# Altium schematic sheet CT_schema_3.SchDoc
size 313 x 185 mm
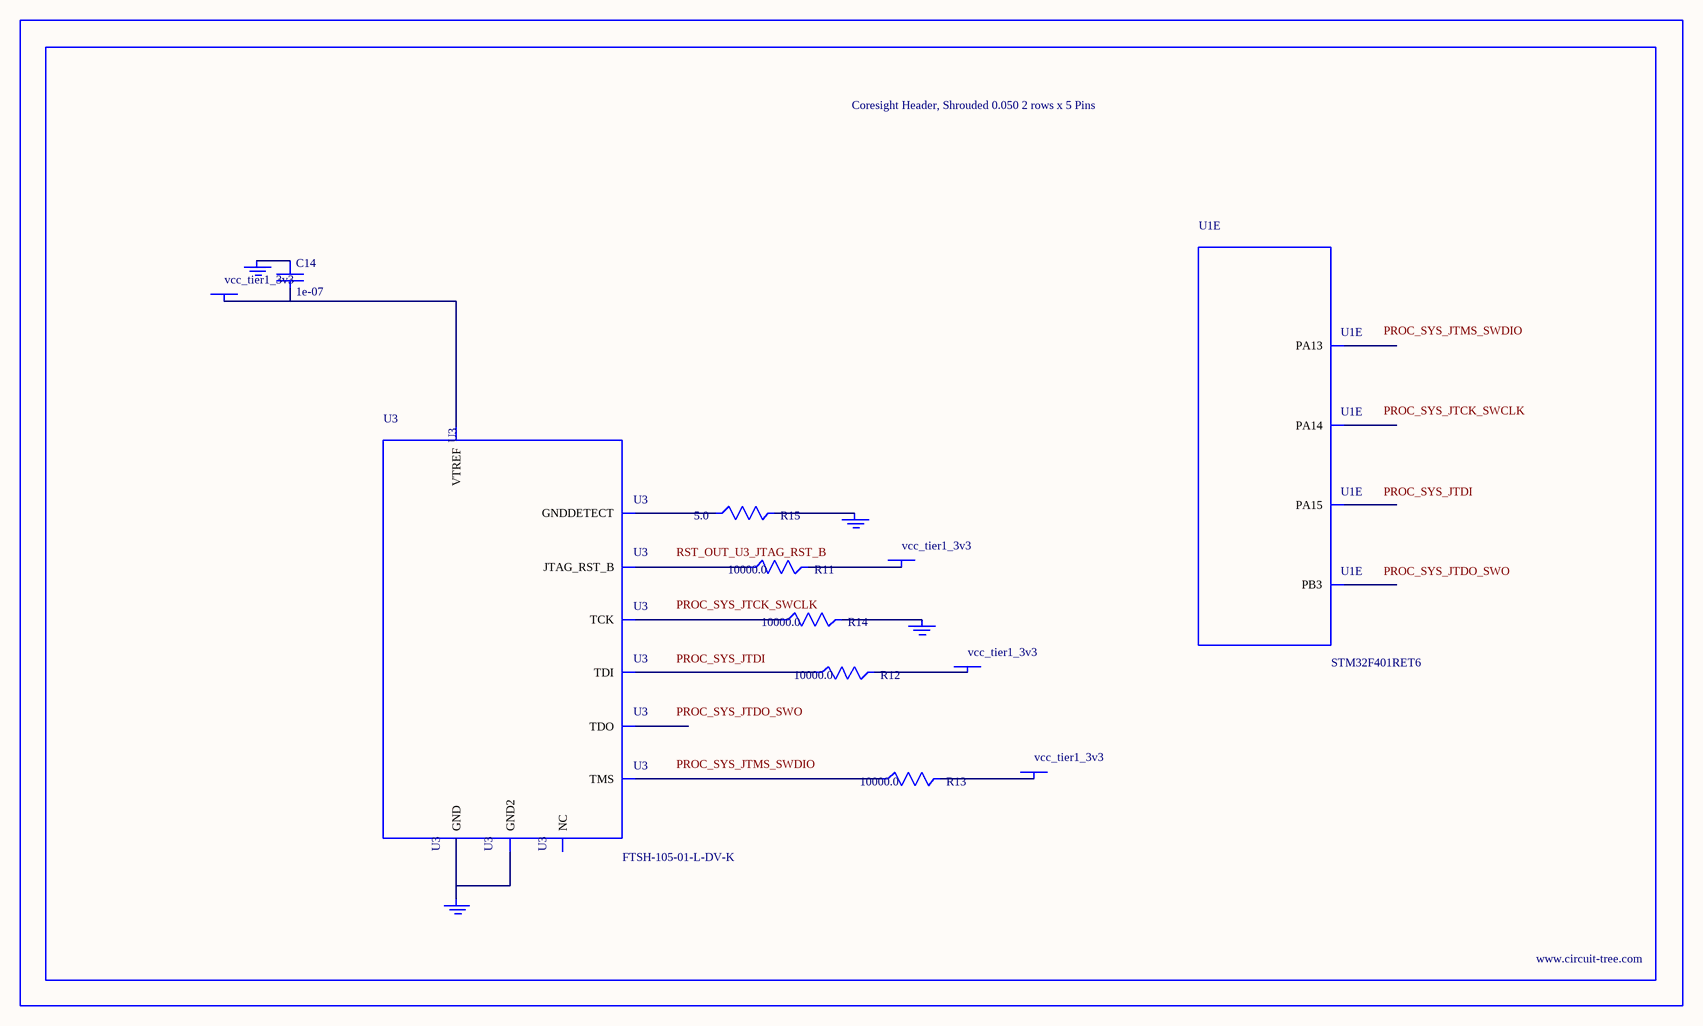
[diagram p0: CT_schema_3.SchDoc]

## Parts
BORDER2  (no value)
C14  1e-07  [C0402]
GND_INSTANCE_2_0  (no value)
GND_INSTANCE_2_1  (no value)
GND_INSTANCE_2_2  (no value)
GND_INSTANCE_2_3  (no value)
POWER_INSTANCE_2_0  vcc_tier1_3v3
POWER_INSTANCE_2_1  vcc_tier1_3v3
POWER_INSTANCE_2_2  vcc_tier1_3v3
POWER_INSTANCE_2_3  vcc_tier1_3v3
R11  10000.0  [R0603]
R12  10000.0  [R0603]
R13  10000.0  [R0603]
R14  10000.0  [R0603]
R15  5.0  [R0603]
U1  STM32F401RET6  [LQFP64]  (part E of 7)
U3  FTSH-105-01-L-DV-K  [SAMTEC_FTSH-105-01-L-DV-K]

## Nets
NetC14_1: C14.1 GND_INSTANCE_2_0.0(GND)
NetC14_2: C14.2 POWER_INSTANCE_2_0.0(PWR) U3.1(VTREF)
NetGND_INSTANCE_2_1_0: GND_INSTANCE_2_1.0(GND) R14.2
NetGND_INSTANCE_2_2_0: GND_INSTANCE_2_2.0(GND) R15.2
NetGND_INSTANCE_2_3_0: GND_INSTANCE_2_3.0(GND) U3.3(GND) U3.5(GND2)
NetPOWER_INSTANCE_2_1_0: POWER_INSTANCE_2_1.0(PWR) R13.2
NetPOWER_INSTANCE_2_2_0: POWER_INSTANCE_2_2.0(PWR) R12.2
NetPOWER_INSTANCE_2_3_0: POWER_INSTANCE_2_3.0(PWR) R11.2
NetR11_1: R11.1 U3.10(JTAG_RST_B)
NetR12_1: R12.1 U3.8(TDI)
NetR13_1: R13.1 U3.2(TMS)
NetR14_1: R14.1 U3.4(TCK)
NetR15_1: R15.1 U3.9(GNDDETECT)

Not connected (* = marked no-connect by the designer): U1 46(PA13) 49(PA14) 50(PA15) 55(PB3); U3 6(TDO) 7(NC)

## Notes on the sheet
- Labels drawn without touching a wire or pin: PROC_SYS_JTCK_SWCLK, PROC_SYS_JTDI, PROC_SYS_JTDO_SWO, PROC_SYS_JTMS_SWDIO, RST_OUT_U3_JTAG_RST_B

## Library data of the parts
BORDER2 = BORDER_PAGE2
C14 = C0402C104K3RACTU
GND_INSTANCE_2_0-GND_INSTANCE_2_3 = GND
POWER_INSTANCE_2_0-POWER_INSTANCE_2_3 = PWR
R11-R14 = RC0603JR-0710KL
R15 = ERJ-3GEYJ5R1V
